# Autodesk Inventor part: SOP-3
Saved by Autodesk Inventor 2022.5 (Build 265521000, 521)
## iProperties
Created: 2024-12
Part Number: SOP-3
Material: Generic
Document SubType Name: Modeling
Designer: AdminForWorker
Density: 1 g/cm^3
Appearance: Default
Title: SOP-3 v1
Author: AdminForWorker
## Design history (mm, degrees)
feature "Body1" [lead]
feature "lead2"
feature "lead1"
feature "lead3"
body "Solid1"
body "Solid2"
body "Solid3"
body "Solid4"
